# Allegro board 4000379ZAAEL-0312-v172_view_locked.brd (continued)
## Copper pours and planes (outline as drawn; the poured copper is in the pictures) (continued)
GND on TOP (solid shape): 66.62,92.71 65.82,92.71 65.82,94.84 66.62,94.84
GND on TOP (solid shape): 128.87,73.77 102.29,73.77 102.29,74.57 128.87,74.57
GND on TOP (solid shape): 66.62,82.91 70.15,82.91 70.15,82.11 65.82,82.11 65.82,86.42 66.62,86.42
GND on TOP (solid shape): 69.42,31.85 68.62,31.85 68.62,41 36.17,41 36.17,41.8 69.42,41.8
GND on TOP (solid shape): 69.42,21.1 50.29,21.1 50.29,21.9 68.62,21.9 68.62,29.74 69.42,29.74
GND on TOP (solid shape): 80.2,105.31 66.62,105.31 66.62,103.01 65.82,103.01 65.82,106.11 80.2,106.11
GND on TOP (solid shape): 89.62,96.38 88.82,96.38 88.82,105.31 82.61,105.31 82.61,106.11 89.62,106.11
GND on TOP (solid shape): 89.62,82.11 72.29,82.11 72.29,82.91 88.82,82.91 88.82,94.24 89.62,94.24
GND on TOP (solid shape): 94.87,74.57 100.15,74.57 100.15,73.77 94.07,73.77 94.07,99.32 94.87,99.32
GND on TOP (solid shape): 113.35,105.27 94.87,105.27 94.87,101.37 94.07,101.37 94.07,106.07 113.35,106.07
GND on TOP (solid shape): 137.07,101.39 136.27,101.39 136.27,105.27 117.79,105.27 117.79,106.07 137.07,106.07
GND on TOP (solid shape): 137.07,73.77 130.91,73.77 130.91,74.57 136.27,74.57 136.27,99.25 137.07,99.25
GND on TOP (solid shape): 24.64,72.64 24.89,72.39 25.91,72.39 26.29,72.01 26.29,65.79 22.86,65.79 22.86,73.91 24.64,73.91
GND on TOP (solid shape): 31.37,77.34 31.37,74.8 30.99,74.42 27.69,74.42 27.43,74.68 27.43,77.6 27.69,77.85 30.86,77.85
GND on TOP (solid shape): 32.77,70.36 32.77,67.18 30.99,67.18 30.23,67.94 30.23,70.1 30.61,70.48 30.61,70.99 32.13,70.99
GND on TOP (solid shape): 34.05,41 15.12,41 15.12,21.9 48.15,21.9 48.15,21.1 14.32,21.1 14.32,41.8 34.05,41.8
GND on TOP (solid shape): 41.72,78.17 41.72,76.14 41.4,75.82 40.01,75.82 39.69,76.14 39.69,77.72 39.75,77.79 40.07,77.79 40.13,77.85 40.13,78.61 41.27,78.61
GND on TOP (solid shape): 136.08,67.88 136.08,67.56 136.14,67.5 136.91,67.5 136.91,66.48 136.33,65.91 134.43,65.91 134.11,66.23 134.11,67.63 134.43,67.94 136.02,67.94
GND on TOP (solid shape): 61.09,74.93 61.09,72.77 60.9,72.58 59.69,72.58 59.56,72.71 59.56,73.6 59.63,73.66 59.82,73.66 60.13,73.98 60.13,74.93 60.26,75.06 60.96,75.06
GND on TOP (solid shape): 72.26,75.37 72.26,72.96 72.07,72.77 70.87,72.77 70.74,72.9 70.74,73.79 70.8,73.85 70.99,73.85 71.31,74.17 71.31,75.31 71.44,75.44 72.2,75.44
GND on BOTTOM (solid shape): 107.44,105.27 103.72,105.27 103.72,106.07 107.44,106.07
GND on BOTTOM (solid shape): 109.54,73.77 102.24,73.77 102.24,74.57 109.54,74.57
GND on BOTTOM (solid shape): 116.87,73.77 112.33,73.77 112.33,74.57 116.87,74.57
GND on BOTTOM (solid shape): 122.28,105.27 118.75,105.27 118.75,106.07 122.28,106.07
GND on BOTTOM (solid shape): 123.84,73.77 120.08,73.77 120.08,74.57 123.84,74.57
GND on BOTTOM (solid shape): 128.85,73.77 126.3,73.77 126.3,74.57 128.85,74.57
GND on BOTTOM (solid shape): 137.07,95.49 136.27,95.49 136.27,99.25 137.07,99.25
GND on BOTTOM (solid shape): 137.07,91.59 136.27,91.59 136.27,94.33 137.07,94.33
GND on BOTTOM (solid shape): 25.42,19.56 63,19.56 63,18.76 24.62,18.76 24.62,35.39 25.42,35.39
GND on BOTTOM (solid shape): 69.42,18.76 65.14,18.76 65.14,19.56 68.62,19.56 68.62,29.72 69.42,29.72
GND on BOTTOM (solid shape): 94.87,74.57 100.12,74.57 100.12,73.77 94.07,73.77 94.07,98.93 94.87,98.93
GND on BOTTOM (solid shape): 95.03,105.27 94.87,105.27 94.87,101.39 94.07,101.39 94.07,106.07 95.03,106.07
GND on BOTTOM (solid shape): 137.07,101.33 136.27,101.33 136.27,105.27 132.34,105.27 132.34,106.07 137.07,106.07
GND on BOTTOM (solid shape): 137.07,73.77 130.99,73.77 130.99,74.57 136.27,74.57 136.27,90.27 137.07,90.27
GND on BOTTOM (solid shape): 69.42,31.88 68.62,31.88 68.62,42.19 25.42,42.19 25.42,37.53 24.62,37.53 24.62,42.99 69.42,42.99
GND on BOTTOM: 39.88,169.62 55.37,169.62 55.37,150.37 59.88,145.86 62.87,145.86 62.87,143.26 64.14,141.99 64.14,122.43 65.53,121.03 145.92,121.03 146.18,121.28 146.18,138.05 135.25,148.97 135.25,167.74 133.74,169.26 145.14,162.48 149.62,150 149.62,20 143.87,6.13 130,0.38 20,0.38 6.13,6.13 0.38,20 0.38,150 5.56,163.28 18.35,169.55 18.35,156.46 19.37,155.45 25.97,155.45 25.97,154.11 27.24,152.84 30.42,152.84 31.05,152.21 32.83,152.21 32.83,152.02 32.32,151.51 32.32,149.48 33.21,148.59 37.66,148.59 38.54,149.48 38.54,151.38 37.97,151.96 37.21,151.96 36.96,152.21 36.96,153.23 38.48,153.23 39.88,154.62 ; 12 cut-outs
GND on L2: 149.62,20 143.87,6.13 130,0.38 20,0.38 6.13,6.13 0.38,20 0.38,150 5.56,163.28 18.35,169.55 18.35,156.46 19.37,155.45 25.97,155.45 25.97,154.11 27.24,152.84 30.42,152.84 31.05,152.21 32.83,152.21 32.83,152.02 32.32,151.51 32.32,149.48 33.21,148.59 37.66,148.59 38.54,149.48 38.54,151.38 37.97,151.96 37.21,151.96 36.96,152.21 36.96,153.23 38.48,153.23 39.88,154.62 39.88,169.62 55.37,169.62 55.37,150.37 59.88,145.86 62.87,145.86 62.87,143.26 64.14,141.99 64.14,122.43 65.53,121.03 145.92,121.03 146.18,121.28 146.18,138.05 135.25,148.97 135.25,167.74 133.74,169.26 145.14,162.48 149.62,150 ; 1 cut-out
GND on L3: 39.88,169.62 55.37,169.62 55.37,150.37 59.88,145.86 62.87,145.86 62.87,143.26 64.14,141.99 64.14,122.43 65.53,121.03 145.92,121.03 146.18,121.28 146.18,138.05 135.25,148.97 135.25,167.74 133.74,169.26 145.14,162.48 149.62,150 149.62,20 143.87,6.13 130,0.38 20,0.38 6.13,6.13 0.38,20 0.38,150 5.56,163.28 18.35,169.55 18.35,156.46 19.37,155.45 25.97,155.45 25.97,154.11 27.24,152.84 30.42,152.84 31.05,152.21 32.83,152.21 32.83,152.02 32.32,151.51 32.32,149.48 33.21,148.59 37.66,148.59 38.54,149.48 38.54,151.38 37.97,151.96 37.21,151.96 36.96,152.21 36.96,153.23 38.48,153.23 39.88,154.62 ; 2 cut-outs
PGND on TOP (solid shape): 10.54,105.54 8.51,105.54 8.51,109.6 10.54,109.6
PGND on TOP (solid shape): 14.48,105.41 12.57,105.41 12.57,109.66 14.48,109.66
PGND on TOP (solid shape): 19.05,136.27 19.05,127.38 18.29,126.62 12.95,126.62 12.45,127.13 12.45,136.72 12.76,137.03 18.29,137.03
PGND on TOP (solid shape): 49.21,98.68 49.21,91.06 48.96,90.81 40.64,90.81 40.13,91.31 40.13,98.81 40.58,99.25 48.64,99.25
PGND on TOP: 50.61,147.38 44.32,147.38 42.04,145.1 32.58,145.1 31.5,144.02 31.5,140.08 29.59,138.18 8.13,138.18 6.22,136.27 6.22,115.32 8.26,113.28 8.26,108.84 5.97,106.55 5.97,92.96 8.13,90.81 55.75,90.81 57.91,92.96 57.91,126.87 59.31,128.27 59.31,138.68 ; 2 cut-outs
PGND on BOTTOM, L3: 51.44,147.38 44.32,147.38 42.04,145.1 32.58,145.1 31.5,144.02 31.5,140.08 29.59,138.18 8.13,138.18 6.22,136.27 6.22,115.32 8.26,113.28 8.26,108.84 5.97,106.55 5.97,92.96 8.13,90.81 55.75,90.81 57.91,92.96 57.91,126.87 58.99,127.95 58.99,139.83
PGND on L2: 50.61,147.38 44.32,147.38 42.04,145.1 32.58,145.1 31.5,144.02 31.5,140.08 29.59,138.18 8.13,138.18 6.22,136.27 6.22,115.32 8.26,113.28 8.26,108.84 5.97,106.55 5.97,92.96 8.13,90.81 55.75,90.81 57.91,92.96 57.91,126.87 59.31,128.27 59.31,138.68
SVDD0_TRX on BOTTOM (solid shape): 78.18,92.35 78.18,91.01 78.05,90.89 77.37,90.89 77.24,91.01 77.24,91.56 77.15,91.65 75.41,91.65 75.29,91.53 75.29,90.71 75.18,90.61 74.32,90.61 74.24,90.68 74.24,92.36 74.28,92.39 78.14,92.39
VCC_0V6_DDR on TOP (solid shape): 129.92,24.84 129.92,23.44 129.95,23.44 130.45,22.94 130.45,21.67 128.12,21.67 127.48,22.3 127.48,24.61 127.81,24.94 129.82,24.94
VCC_0V6_DDR on BOTTOM (solid shape): 125.6,33.99 125.6,25.68 126.34,24.94 128.85,24.94 129.11,24.69 129.11,22.43 128.75,22.07 126.21,22.07 125.6,21.46 125.6,18.48 125.33,18.21 122.22,18.21 121.91,18.52 121.91,18.9 122.22,19.21 123.53,19.21 123.85,19.53 123.85,26.4 122.05,26.4 122.05,32.12 121.73,32.44 117.05,32.44 116.73,32.76 116.73,34.07 117.05,34.39 125.2,34.39
VCC_0V9_PRX321 on TOP (solid shape): 128.1,58.15 128.09,58.14 125.82,58.14 124.65,59.31 124.65,61.59 125.46,62.41 128.1,62.41
VCC_0V9_PRX321 on BOTTOM: 101.47,57.98 101.47,54.15 102.16,53.47 102.16,52.45 101.73,52.02 101.73,50.9 103.86,48.77 105.36,48.77 105.46,48.87 105.46,49.23 105.18,49.5 105.18,52.3 104.39,53.09 103.58,53.09 102.55,54.11 102.55,55.69 102.74,55.88 103.19,55.88 103.25,55.94 103.25,57.47 103.95,58.17 109.92,58.17 111.38,59.63 126.3,59.63 126.5,59.82 126.5,60.9 126.13,61.26 111.11,61.26 109.54,59.69 103.19,59.69
VCC_0V9_PRX321_XFI on BOTTOM (solid shape): 103.31,55.56 103.31,54.36 103.57,54.1 103.57,53.85 103.36,53.63 103.21,53.63 102.74,54.1 102.74,55.63 103.25,55.63
VCC_1V0_8261BE on TOP (solid shape): 69.34,89.41 69.34,87.44 68.96,87.06 65.41,87.06 64.64,86.3 64.64,83.82 64.45,83.63 62.74,83.63 62.55,83.82 62.55,88.07 64.2,89.73 69.02,89.73
VCC_1V0_8261BE on TOP (solid shape): 76.19,91.15 76.19,90.88 76.07,90.76 75.79,90.76 75.67,90.63 75.67,86.82 75.56,86.72 74.35,86.72 74.27,86.8 74.27,88.18 75.03,88.94 75.03,90.91 75.43,91.31 76.03,91.31
VCC_1V0_8261BE on BOTTOM (solid shape): 75.67,89.95 75.67,87.16 75.56,87.06 74.42,87.06 74.27,87.21 74.27,90.1 75.51,90.1
VCC_1V0_8261BE on BOTTOM (solid shape): 70.1,91.44 70.1,87.25 69.91,87.06 68.33,87.06 68.07,87.31 68.07,91.38 68.45,91.76 69.79,91.76
VCC_1V0_8261BE on BOTTOM (solid shape): 84.14,89.1 84.14,88.26 84.02,88.14 81.2,88.14 81.08,88.27 81.08,89.18 81.15,89.26 83.97,89.26
VCC_1V0_8261BE on BOTTOM (solid shape): 85.7,95.92 85.7,93.81 85.6,93.71 84.23,93.71 84.23,94.75 83.9,95.08 83.9,95.92 83.97,95.99 85.62,95.99
VCC_1V0_8261BE on BOTTOM (solid shape): 72.14,102.55 72.14,101.41 72.32,101.22 72.92,101.22 73.03,101.12 73.03,100.34 73,100.31 70.28,100.31 70.23,100.36 70.23,102.49 70.48,102.74 71.95,102.74
VCC_1V0_8261BE on L3: 68.71,102.74 71.95,102.74 72.14,102.55 72.14,100.39 71.02,99.28 71.02,90.35 72.36,89.01 73.41,89.01 74.75,90.35 79.67,90.35 80.19,90.87 80.19,94.9 84.2,94.9 84.2,88.33 83.61,87.74 76.91,87.74 76.23,87.05 68.33,87.05 68.07,87.31 68.07,102.11
VCC_1V9_8261BE on TOP (solid shape): 88.2,80.2 88.2,77.79 87.88,77.47 82.55,77.47 82.55,80.07 82.99,80.52 87.88,80.52
VCC_1V9_8261BE on BOTTOM (solid shape): 72.01,97.11 72.01,92.27 71.88,92.14 71.37,92.14 71.25,92.27 71.25,97.13 71.35,97.24 71.88,97.24
VCC_1V9_8261BE on BOTTOM (solid shape): 93.29,104.7 93.29,101.8 93.09,101.6 87.76,101.6 87.25,102.11 87.25,104.78 87.63,105.16 92.84,105.16
VCC_1V9_8261BE on BOTTOM (solid shape): 83.31,103.03 83.31,100.46 83.24,100.39 80.9,100.39 80.85,100.44 80.85,101.58 80.64,101.78 79.98,101.78 79.98,103.31 80.06,103.38 82.96,103.38
VCC_1V9_8261BE on L3: 74.68,90.58 79.47,90.58 80.01,91.12 80.01,95.03 83.82,95.03 83.82,100.84 84.07,101.1 87.69,101.1 88.33,100.46 88.33,83.19 85.47,80.33 85.47,77.98 85.98,77.47 87.88,77.47 91.69,81.28 91.69,99.69 93.29,101.3 93.29,103.36 93.07,103.59 81.86,103.59 81.23,102.95 81.23,96.65 78.38,96.65 78.38,92.56 72.9,92.56 72.67,92.79 72.67,97.21 71.35,97.21 71.2,97.06 71.2,90.56 72.49,89.26 73.36,89.26
VCC_1V35_DDR on TOP (solid shape): 135,30.61 135,28.51 134.68,28.19 131.04,28.19 130.09,29.15 130.09,30.87 134.73,30.87
VCC_1V35_DDR on BOTTOM (solid shape): 108.06,46.94 111.43,46.94 111.63,46.74 111.63,46.35 107.82,46.35 107.7,46.48 107.7,46.8 107.51,46.99 107.06,46.99 106.81,46.74 106.81,46.55 106.68,46.42 106.08,46.42 105.77,46.74 105.77,46.9 106.36,47.5 107.51,47.5
VCC_1V35_DDR on L3: 131.57,30.86 134.87,30.86 136.53,29.21 136.53,16.76 130.68,10.92 89.53,10.92 81.28,19.18 81.28,37.85 91.95,48.51 103.31,48.51 104.71,47.12 105.22,47.12 105.79,47.69 107.63,47.69 110.3,45.02 110.3,40.7 116.4,34.61 125.6,34.61 126.11,34.1 126.11,18.03 127.44,16.7 129.16,16.7 130.81,18.35 130.81,30.1
VCC_3V3_8261BE on BOTTOM (solid shape): 68.01,86.61 68.9,86.61 69.02,86.49 69.02,84.84 67.18,84.84 66.87,85.15 66.87,86.8 67.82,86.8
VCC_3V3_PON on TOP (solid shape): 54.8,83.5 54.8,64.96 51.63,64.96 51.63,83.38 52.01,83.76 54.55,83.76
VCC_3V3_PON on TOP (solid shape): 140.58,28.85 140.58,27.33 140.3,27.05 137.19,27.05 137.07,27.17 137.07,28.91 137.26,29.1 140.34,29.1
VCC_3V3_PON on TOP (solid shape): 65.79,32.19 66.8,32.19 66.93,32.07 66.93,29.46 66.87,29.4 64.6,29.4 64.53,29.47 64.53,31.97 64.87,32.32 65.66,32.32
VCC_3V3_PON on BOTTOM (solid shape): 126.01,77.14 126.01,72.06 125.5,71.55 124.43,71.55 124.03,71.96 124.03,77.29 125.86,77.29
VCC_3V3_PON on BOTTOM (solid shape): 66.9,31.32 66.9,30.43 66.7,30.23 65.68,30.23 65.51,30.4 65.51,31.19 65.81,31.5 66.73,31.5
VCC_3V3_PON on BOTTOM (solid shape): 47.69,34.73 47.69,31.62 48.07,31.24 48.9,31.24 49.15,30.99 49.15,29.91 48.96,29.72 46.42,29.72 46.23,29.91 46.23,34.73 46.42,34.92 47.5,34.92
VCC_3V3_PON on L3 (solid shape): 141.11,28.38 141.11,27.25 138.67,27.25 138.34,27.58 138.34,28.69 138.52,28.87 140.63,28.87
VCC_3V3_PON on L3 (solid shape): 66.9,31.32 66.9,30.45 65.96,29.51 65.2,29.51 64.99,29.72 64.99,30.67 65.82,31.5 66.73,31.5
VCC_3V3_PON on L3 (solid shape): 126.03,72.87 126.03,66.45 126.26,66.22 126.26,64.97 123.72,64.97 123.72,66.14 124.03,66.45 124.03,73.03 124.28,73.28 125.63,73.28
VCC_3V3_PON on L3: 52.83,67.37 52.83,49.78 43.69,40.64 43.69,20.07 44.13,19.62 65.72,19.62 66.48,20.38 66.48,22.67 65.02,22.67 65.02,22.16 63.94,21.08 47.56,21.08 46.86,21.78 46.86,28.89 47.69,29.72 47.69,33.91 47.43,34.16 46.48,34.16 46.04,34.61 46.04,39.62 54.8,48.39 54.8,67.37
VCC_20V0_SYS on TOP (solid shape): 19.62,147.7 19.62,141.73 19.24,141.35 14.92,141.35 14.67,141.6 14.67,147.38 15.18,147.89 19.43,147.89
VCC_20V0_SYS on TOP (solid shape): 70.87,63.56 70.87,61.85 70.61,61.59 68.52,61.59 68.14,61.98 68.14,63.63 68.45,63.94 70.48,63.94
VCC_20V0_SYS on TOP (solid shape): 93.66,75.82 93.66,75.5 79.76,61.59 79.44,61.59 78.93,62.1 78.93,62.55 92.77,76.39 93.09,76.39
VCC_20V0_SYS on TOP (solid shape): 131.64,45.91 131.64,43.43 131.38,43.18 129.92,43.18 129.54,43.56 129.54,45.91 129.79,46.16 131.38,46.16
VCC_20V0_SYS on TOP (solid shape): 100.71,83.25 100.71,82.19 100.5,81.98 98.03,81.98 97.28,81.23 97.28,78.93 97.09,78.74 96.27,78.74 96.01,78.99 96.01,81.84 97.61,83.44 100.52,83.44
VCC_20V0_SYS on TOP (solid shape): 123.63,66.87 123.63,59.37 125.54,57.47 128.52,57.47 128.71,57.28 128.71,56.13 128.46,55.88 124.78,55.88 121.86,58.8 121.86,66.93 122.05,67.12 123.38,67.12
VCC_20V0_SYS on TOP (solid shape): 22.08,77.2 22.08,63.71 23.69,62.1 31.88,62.1 33.72,63.94 58.99,63.94 59.37,63.56 59.37,61.85 59.12,61.59 42.16,61.59 41.02,60.45 41.02,56.13 39.88,54.99 17.8,54.99 16.31,56.48 16.31,77.52 16.52,77.72 21.56,77.72
VCC_20V0_SYS on L3 (solid shape): 123.63,63.06 123.32,62.74 121.28,62.74 121.28,64.01 123.63,64.01
VCC_20V0_SYS on L3 (solid shape): 82.36,62.74 80.9,62.74 79.76,61.59 57.02,61.59 56.64,61.98 56.64,63.63 57.02,64.01 82.36,64.01
VCC_20V0_SYS on L3 (solid shape): 97.28,81.34 97.28,79.12 91.88,73.72 91.5,73.72 90.93,74.3 90.93,74.55 96.01,79.63 96.01,81.34 96.2,81.53 97.09,81.53
VCC_20V0_SYS on L3 (solid shape): 131.64,56.07 131.64,45.02 131.38,44.77 129.73,44.77 129.54,44.96 129.54,55.63 129.29,55.88 127.44,55.88 127.19,56.13 127.19,57.21 127.44,57.47 130.24,57.47
VCC_20V0_SYS on L3: 19.37,144.4 19.62,144.15 19.62,141.73 19.24,141.35 5.84,141.35 3.81,139.32 3.81,75.31 5.46,73.66 19.81,73.66 20.19,73.28 20.19,70.36 19.81,69.98 3.81,69.98 1.02,72.77 1.02,140.59 4.83,144.4
VCC_20V0_USB_PD on TOP (solid shape): 26.23,160.4 26.23,157.16 25.78,156.72 19.11,156.72 19.11,160.34 20.19,161.42 25.21,161.42
VCC_20V0_USB_PD on L3: 34.95,161.8 34.95,166.04 34.24,166.75 31.04,166.75 29.95,165.66 29.95,162.51 29.54,162.1 26.24,162.1 25.55,161.42 21.78,161.42 21.4,161.04 21.4,159.13 21.7,158.83 25.98,158.83 27.5,160.34 30.73,160.34 31.11,160.72 31.11,165.1 31.88,165.86 33.07,165.86 33.73,165.2 33.73,161.7 33.86,161.57 34.72,161.57
VDD_RX on BOTTOM (solid shape): 50.46,30.91 50.46,30.05 50.93,29.59 51.88,29.59 52.07,29.4 52.07,28.83 51.75,28.51 49.72,28.51 49.53,28.7 49.53,30.85 49.66,30.99 50.39,30.99
VDD_RX2 on TOP (solid shape): 67.06,28.57 67.06,23.51 66.92,23.36 65.89,23.36 65.82,23.44 65.82,26.62 65.74,26.7 64.73,26.7 64.62,26.81 64.62,27.65 64.52,27.75 64.52,28.51 64.96,28.96 66.67,28.96
VDD_TX on BOTTOM (solid shape): 50.29,37.18 50.29,35.88 49.78,35.37 46.55,35.37 46.42,35.5 46.42,37.53 46.55,37.66 49.82,37.66
VDD_TX on L3: 59.03,37.54 59.03,34.59 56.38,31.94 54.55,31.94 53.02,33.46 49.85,33.46 47.75,35.56 47.75,37.59 49.02,38.86 57.71,38.86
(no net) on TOP: 39.88,169.62 55.37,169.62 55.37,150.37 59.88,145.86 62.87,145.86 62.87,143.26 64.14,141.99 64.14,122.43 65.53,121.03 145.92,121.03 146.18,121.28 146.18,138.05 135.25,148.97 135.25,167.74 133.74,169.26 145.14,162.48 149.62,150 149.62,20 143.87,6.13 130,0.38 20,0.38 6.13,6.13 0.38,20 0.38,150 5.56,163.28 18.35,169.55 18.35,156.46 19.37,155.45 25.97,155.45 25.97,154.11 27.24,152.84 30.42,152.84 31.05,152.21 32.83,152.21 32.83,152.02 32.32,151.51 32.32,149.48 33.21,148.59 37.66,148.59 38.54,149.48 38.54,151.38 37.97,151.96 37.21,151.96 36.96,152.21 36.96,153.23 38.48,153.23 39.88,154.62 ; 17 cut-outs
DUT_AVDDHC_3V3 on TOP (solid shape): 122.3,100 122.3,95.71 121.03,94.43 121.03,93.34 120.61,92.92 117.54,92.92 117.1,93.37 116.29,93.37 115.97,93.05 114.51,93.05 114.45,93.11 114.45,94.38 114.77,94.7 116.9,94.7 117.32,94.28 117.32,93.88 117.63,93.57 118.85,93.57 119.21,93.94 119.21,95.65 120.73,97.17 120.73,99.59 120.37,99.95 120.27,99.95 120.27,100.46 121.84,100.46
DUT_AVDDHC_3V3 on TOP (solid shape): 121.75,89.7 121.75,89.06 121.23,88.54 120.35,88.54 118.58,86.76 116.42,86.76 116.29,86.89 115.4,86.89 115.02,86.51 114.83,86.51 114.09,87.24 112.33,87.24 110.07,84.98 108.1,84.98 107.7,84.58 107.7,83.44 107.31,83.06 105.66,83.06 105.47,83.25 105.47,85.47 106.02,86.02 109.39,86.02 111.27,87.9 111.27,88.67 111.08,88.86 111.08,89.11 111.21,89.24 114.96,89.24 116.73,87.46 117.88,87.46 120.35,89.94 121.51,89.94
DUT_AVDDHC_3V3 on BOTTOM (solid shape): 99.34,84.07 99.52,83.9 106.79,83.9 107.11,83.58 107.11,83.34 106.83,83.06 101.73,83.06 101.27,82.6 101.27,79.91 100.81,79.91 98.68,82.04 98.68,84.76 99.34,84.76
DUT_AVDDLC_0V95 on TOP (solid shape): 122.64,91.14 122.64,90.64 122.35,90.34 121.51,90.34 121.31,90.55 121.31,91.16 121.48,91.33 122.45,91.33
DUT_AVDDLC_0V95 on TOP (solid shape): 114.19,86.57 114.19,85.11 114.13,85.05 112.73,85.05 112.54,84.86 112.54,82.19 112.29,81.94 109.94,81.94 109.62,82.25 109.62,83.78 109.94,84.09 110.7,84.09 110.83,84.22 110.83,85.12 112.47,86.76 114,86.76
DUT_AVDDLC_0V95 on TOP (solid shape): 127.71,93.57 134.52,93.57 134.8,93.29 134.8,92.58 134.52,92.3 126.72,92.3 126.58,92.16 124.99,92.16 124.23,92.92 123.66,92.92 123.47,92.73 123.47,92.55 121.64,92.55 121.43,92.76 121.43,94.06 121.56,94.19 121.81,94.19 122.13,93.87 123.4,93.87 124.1,94.57 126.71,94.57
DUT_AVDDLC_0V95 on TOP (solid shape): 123.98,88.47 123.98,88.06 123.63,87.71 123.39,87.71 123.19,87.51 123.19,86.21 123.8,85.6 124.26,85.6 125.3,84.56 132.33,84.56 132.33,83.14 121.24,83.14 120.95,83.43 120.95,84.03 123.17,84.03 123.6,84.45 123.6,84.84 122.89,85.55 121.79,85.55 121.36,85.98 121.36,86.33 121.64,86.61 121.64,87.63 121.33,87.94 121.33,88.08 121.48,88.24 121.64,88.24 122.07,88.67 123.78,88.67
DUT_AVDDLC_0V95 on TOP (solid shape): 106.07,100.56 106.07,98.88 106.76,98.2 115.92,98.2 116.13,97.99 116.13,96.08 116.02,95.98 115.54,95.98 115.43,96.1 115.43,96.51 115.19,96.75 109.17,96.75 108.74,96.32 108.74,95.25 109.37,94.61 113.48,94.61 114.04,94.05 114.04,91.32 114.3,91.06 114.3,89.96 114.12,89.78 113.74,89.78 113.64,89.89 113.64,90.22 113.46,90.39 113.05,90.39 112.95,90.49 112.95,91.19 113.26,91.49 113.26,92.27 113.08,92.45 109.86,92.45 108.92,93.4 108.15,93.4 106.81,94.74 104.06,94.74 103.45,95.35 103.45,98.96 103.2,99.21 102.23,99.21 101.92,99.53 101.92,101.22 102.11,101.41 105.22,101.41
EAR_GND on TOP, L2: 57.48,169.62 130,169.62 130.51,169.61 131.02,169.59 133.48,167.13 133.48,148.21 144.27,137.41 144.27,123 144.02,122.75 141.86,122.75 141.48,123.13 141.48,134.62 130.43,145.67 130.43,157.48 125.35,162.56 125.35,165.48 123.95,166.88 113.03,166.88 111.89,165.74 111.89,162.69 111.12,161.93 109.47,161.93 108.58,162.81 108.58,166.12 107.82,166.88 95.89,166.88 95.25,166.24 95.25,162.69 94.49,161.93 92.84,161.93 91.95,162.81 91.95,165.61 90.68,166.88 79.25,166.88 78.61,166.24 78.61,162.69 77.85,161.93 76.07,161.93 75.31,162.69 75.31,165.99 74.42,166.88 63.25,166.88 61.59,165.23 61.59,162.43 60.45,161.29 60.45,151.26 62.87,148.84 62.87,147.51 60.77,147.51 57.15,151.13 57.15,169.29
EAR_GND on BOTTOM: 57.48,169.62 130,169.62 130.51,169.61 131.02,169.59 133.48,167.13 133.48,148.21 135.38,146.3 135.38,144.4 134.75,143.76 132.33,143.76 130.43,145.67 130.43,157.48 125.35,162.56 125.35,165.48 123.95,166.88 113.03,166.88 111.89,165.74 111.89,162.69 111.12,161.93 109.47,161.93 108.58,162.81 108.58,166.12 107.82,166.88 95.89,166.88 95.25,166.24 95.25,162.69 94.49,161.93 92.84,161.93 91.95,162.81 91.95,165.61 90.68,166.88 79.25,166.88 78.61,166.24 78.61,162.69 77.85,161.93 76.07,161.93 75.31,162.69 75.31,165.99 74.42,166.88 63.25,166.88 61.59,165.23 61.59,162.43 60.45,161.29 60.45,151.26 62.87,148.84 62.87,147.51 60.77,147.51 57.15,151.13 57.15,169.29
EAR_GND on BOTTOM, L3: 135.25,146.43 65.28,146.43 61.59,150.11 59.88,148.4 64.77,143.51 132.59,143.51 141.48,134.62 141.48,126.36 141.1,125.98 64.9,125.98 64.64,125.73 64.64,122.94 64.77,122.81 143.89,122.81 144.4,123.32 144.4,137.29
EAR_GND on L3: 57.48,169.62 130,169.62 130.51,169.61 131.02,169.59 133.48,167.13 133.48,148.21 135.38,146.3 135.38,144.4 134.75,143.76 132.33,143.76 130.43,145.67 130.43,157.48 125.35,162.56 125.35,165.48 123.95,166.88 113.03,166.88 111.89,165.74 111.89,162.69 111.12,161.93 109.47,161.93 108.58,162.81 108.58,166.12 107.82,166.88 95.89,166.88 95.25,166.24 95.25,162.69 94.49,161.93 92.84,161.93 91.95,162.81 91.95,165.61 90.68,166.88 79.25,166.88 78.61,166.24 78.61,162.69 77.85,161.93 76.07,161.93 75.31,162.69 75.31,165.99 74.42,166.88 63.25,166.88 61.59,165.23 61.59,162.43 60.45,161.29 60.45,151.26 62.93,148.78 62.93,147.57 62.8,147.45 60.83,147.45 57.15,151.13 57.15,169.29
PSE_54V0_P2- on TOP (solid shape): 52.32,143.38 52.32,140.72 52.01,140.4 42.86,140.4 41.91,141.35 41.91,143.45 42.04,143.57 52.13,143.57
PSE_54V0_P3- on TOP (solid shape): 57.15,129.92 57.15,128.84 56.83,128.52 49.53,128.52 48.83,129.22 46.61,129.22 46.61,130.68 47.24,131.32 55.75,131.32
UPGND on TOP, BOTTOM, L2, L3: 19.49,169.67 38.67,169.67 39.12,169.23 39.12,154.94 38.16,153.99 36.32,153.99 36.2,153.86 36.2,151.83 36.58,151.45 37.4,151.45 37.78,151.07 37.78,149.8 37.34,149.35 33.53,149.35 33.08,149.8 33.08,151.19 33.59,151.7 33.59,152.72 33.34,152.97 31.37,152.97 30.73,153.61 27.56,153.61 26.73,154.43 26.73,155.83 26.35,156.21 19.68,156.21 19.11,156.78 19.11,169.29
VOUT on TOP (solid shape): 24.96,153.48 24.96,151.64 25.27,151.32 27.43,151.32 27.43,149.35 27.05,148.97 15.49,148.97 15.37,149.1 15.37,153.16 15.88,153.67 24.77,153.67
VREFCA on TOP (solid shape): 136.35,20.75 136.35,19.61 136.12,19.38 131.65,19.38 130.58,18.31 130.58,17.37 130.33,17.12 128.75,17.12 128.47,17.4 128.47,20.37 128.6,20.5 130.23,20.5 130.73,21.01 136.09,21.01
VREFCA on BOTTOM (solid shape): 130.61,18.67 130.61,17.12 127.58,17.12 127.43,17.28 127.43,18.54 128.22,19.33 129.95,19.33
N18711395 on TOP (solid shape): 62.97,26.44 62.97,25.5 62.84,25.38 62.04,25.38 60.22,23.56 56.71,23.56 56.64,23.62 56.64,25.27 57.59,26.23 60.83,26.23 61.09,26.48 62.93,26.48
N18711397 on TOP (solid shape): 64.32,26.6 64.32,23.45 64.23,23.37 61.92,23.37 61.66,23.63 61.66,24.78 62.06,25.18 62.91,25.18 63.12,25.38 63.12,26.58 63.21,26.67 64.24,26.67
N18712445 on BOTTOM (solid shape): 54.17,31.37 54.17,30.9 53.43,30.16 52.26,30.16 52.07,29.97 51.05,29.97 50.86,30.16 50.86,30.86 50.99,30.99 53.02,30.99 53.59,31.56 53.98,31.56
N19149157 on TOP (solid shape): 133.32,24.79 133.32,23.55 133.17,23.39 130.45,23.39 130.4,23.44 130.4,25.02 130.48,25.1 133.02,25.1
N19149173 on TOP (solid shape): 136.21,23.3 136.21,21.4 136.08,21.27 135.51,21.27 135.38,21.4 135.38,23.24 135.57,23.43 136.08,23.43
N19149206 on TOP (solid shape): 136.59,24.38 135.57,24.38 135.45,24.51 135.45,28.64 136.59,28.64
N19149219 on TOP (solid shape): 133.73,27.75 133.73,25.97 134.18,25.53 134.18,24.38 133.54,24.38 133.48,24.45 133.48,24.96 132.78,25.65 132.78,27.56 133.03,27.81 133.67,27.81
N19149964 on TOP (solid shape): 9.63,60.02 9.63,56.39 9.23,55.99 6.08,55.99 5.7,56.37 5.7,60.18 6.1,60.58 9.07,60.58
N19149982 on TOP (solid shape): 12.58,60.35 12.58,57.99 11.78,57.2 11.78,51.76 11.48,51.45 10.27,51.45 9.95,51.77 9.95,60.08 10.46,60.59 12.33,60.59
N19164772 on BOTTOM (solid shape): 46.8,130.24 46.8,127.95 46.67,127.83 41.27,127.83 41.02,128.08 41.02,130.43 41.15,130.56 46.48,130.56
N19164775 on TOP (solid shape): 43.05,128.4 48.32,128.4 48.64,128.08 48.64,126.11 48.32,125.79 41.97,125.79 40.83,126.94 40.83,129.22 40.89,129.29 42.16,129.29
N19165359 on BOTTOM (solid shape): 43.94,134.94 43.94,130.94 43.75,130.75 41.08,130.75 40.96,130.87 40.96,134.87 41.21,135.13 43.75,135.13
N19165523 on TOP (solid shape): 48.7,134.87 48.7,132.02 48.39,131.7 46.99,131.7 45.53,130.24 43.56,130.24 43.37,130.43 43.37,134.68 43.69,135 48.58,135
N19165523 on BOTTOM (solid shape): 48.7,134.87 48.7,133.1 48.58,132.97 46.61,132.97 46.42,133.16 46.42,134.87 46.55,135 48.58,135
N19177080 on BOTTOM (solid shape): 43.88,139.51 43.88,135.38 43.75,135.25 41.21,135.25 40.96,135.51 40.96,139.51 41.21,139.76 43.62,139.76
N19177140 on TOP (solid shape): 48.77,139.7 48.77,135.64 48.45,135.32 43.43,135.32 43.37,135.38 43.37,139.95 43.56,140.14 48.32,140.14
N19177140 on BOTTOM (solid shape): 48.77,138.49 48.77,136.59 48.7,136.53 46.67,136.53 46.42,136.78 46.42,138.49 46.67,138.75 48.51,138.75
N19177597 on BOTTOM (solid shape): 38.93,142.37 38.93,141.6 38.61,141.29 37.59,141.29 37.15,140.84 37.15,140.08 36.89,139.83 33.91,139.83 33.08,140.65 33.08,142.05 33.66,142.62 38.67,142.62
N19177618 on TOP (solid shape): 39.43,143.51 40.2,143.51 40.39,143.32 40.39,141.48 40.32,141.41 34.1,141.41 33.66,141.86 33.66,144.15 33.85,144.34 38.61,144.34
N19198143 on TOP (solid shape): 29.02,131.64 29.02,125.41 29.21,125.22 30.86,125.22 31.11,124.97 31.11,122.75 30.86,122.49 26.48,122.49 26.29,122.68 26.29,131.25 26.73,131.7 28.96,131.7
N19198187 on TOP (solid shape): 35.31,121.41 35.31,117.28 34.29,116.27 26.86,116.27 26.04,117.09 26.04,119 32.19,119 33.02,118.17 34.23,118.17 34.35,118.3 34.35,121.35 34.54,121.54 35.18,121.54
N19198218 on TOP (solid shape): 38.04,121.22 39.05,121.22 39.88,120.4 49.78,120.4 50.16,120.02 50.16,117.41 49.66,116.9 37.4,116.9 36.83,117.47 36.83,121.41 37.85,121.41
N19198237 on TOP (solid shape): 41.72,125.54 42.67,125.54 42.99,125.22 42.99,124.46 42.86,124.33 40.51,124.33 39.81,125.03 37.08,125.03 36.89,125.22 36.89,126.94 37.02,127.06 40.2,127.06
N19198365 on TOP (solid shape): 34.04,121.41 34.04,118.55 33.91,118.43 33.15,118.43 32.83,118.75 32.83,121.48 32.96,121.6 33.85,121.6
N19201777 on TOP (solid shape): 14.35,77.47 14.35,73.41 13.84,72.9 11.81,72.9 11.18,72.26 11.18,70.36 11.56,69.98 12.7,69.98 13.08,69.6 13.08,62.74 5.59,62.74 4.95,63.37 4.95,77.34 5.33,77.72 14.1,77.72
N19201879 on TOP (solid shape): 26.29,77.09 26.29,72.77 26.16,72.64 25.15,72.64 24.89,72.9 24.89,73.91 23.75,75.06 23.75,77.34 24.13,77.72 25.65,77.72
N19202018 on TOP (solid shape): 15.75,71.88 15.75,64.14 14.48,64.14 13.84,64.77 13.84,69.6 13.08,70.36 12.06,70.36 11.94,70.48 11.94,72.14 12.06,72.26 15.37,72.26
N19202225 on TOP (solid shape): 27.62,113.54 31.88,113.54 32,113.41 32,111.12 31.62,110.74 25.4,110.74 24.57,111.57 24.57,112.59 24.19,112.97 22.23,112.97 22.03,112.78 22.03,111.19 21.78,110.93 18.8,110.93 18.35,110.49 18.35,108.71 15.81,108.71 13.08,111.44 13.08,120.21 13.4,120.52 20.64,120.52
N19202261 on TOP (solid shape): 53.85,112.52 53.85,106.74 52.32,105.22 40.83,105.22 39.5,106.55 39.5,109.6 38.35,110.74 32.89,110.74 32.51,111.12 32.51,113.41 32.64,113.54 52.83,113.54
N19202468 on TOP (solid shape): 24.26,112.46 24.26,111.51 25.27,110.49 28.57,110.49 29.34,109.73 29.34,105.54 23.75,105.54 23.75,107.89 22.48,109.16 22.48,112.52 22.61,112.65 24.07,112.65
N19492059 on TOP (solid shape): 135.25,69.72 135.25,68.83 135.45,68.64 136.72,68.64 136.78,68.58 136.78,68.26 136.72,68.2 134.43,68.2 133.92,67.69 122.07,67.69 122.07,69.27 122.76,69.95 135.03,69.95
N19492096 on TOP (solid shape): 144.27,61.91 144.27,60.2 142.21,58.14 129.21,58.14 129.21,62.23 143.95,62.23
N19492579 on TOP (solid shape): 144.34,67.63 144.34,65.6 144.08,65.34 137.99,65.34 137.99,67.56 137.86,67.69 136.4,67.69 136.33,67.75 136.33,68.01 138.24,68.01 138.68,68.45 143.51,68.45
N19492605 on TOP (solid shape): 138.81,68.83 138.18,68.2 137.1,68.2 137.1,68.58 137.16,68.64 137.48,68.64 137.73,68.9 137.73,69.34 137.92,69.53 138.81,69.53
N19494174 on TOP (solid shape): 133.39,32.75 132.64,32 130.21,32 129.97,32.25 129.97,39.34 133.39,39.34
N19494229 on TOP (solid shape): 137.52,40.07 137.71,39.88 138.34,39.88 138.4,39.81 138.4,39.56 129.92,39.56 129.92,42.55 137.52,42.55
N19494302 on TOP (solid shape): 138.4,38.99 137.35,38.99 137.35,37.38 137.47,37.25 137.47,35.75 136.63,34.9 134.75,34.9 134.75,39.19 134.92,39.37 138.4,39.37
N19496414 on TOP (solid shape): 39.5,78.42 39.5,76.14 40.01,75.63 40.01,64.77 39.75,64.52 38.04,64.52 37.66,64.9 37.66,76.64 37.97,76.96 38.86,76.96 39.05,77.15 39.05,78.42 39.12,78.49 39.43,78.49
N19496646 on TOP (solid shape): 50.61,85.09 50.61,72.83 50.29,72.52 47.18,72.52 46.74,72.96 46.74,86.17 46.86,86.3 49.4,86.3
N19496749 on TOP (solid shape): 43.05,86.11 43.05,79.76 42.99,79.69 40.13,79.69 40.01,79.57 40.01,78.11 39.94,78.04 39.69,78.04 39.69,79.95 39.24,80.39 39.24,85.22 40.2,86.17 42.99,86.17
N19496764 on TOP (solid shape): 39.5,79.88 39.5,78.8 39.12,78.8 39.05,78.87 39.05,79.18 38.8,79.44 38.35,79.44 38.16,79.63 38.16,80.52 38.86,80.52
N19531807 on TOP (solid shape): 26.86,152.97 28.89,152.97 28.89,151.57 28.83,151.51 25.72,151.51 25.53,151.7 25.53,153.29 25.59,153.35 26.48,153.35
N19561994 on TOP (solid shape): 65.15,82.36 65.15,74.8 64.9,74.55 62.93,74.55 62.48,74.99 62.48,82.36 62.67,82.55 64.96,82.55
N19562054 on TOP (solid shape): 58.86,71.69 59.18,71.37 59.18,64.83 58.8,64.45 57.28,64.45 56.96,64.77 56.96,71.63 57.4,72.07 58.04,72.07 58.61,72.64 58.61,73.34 58.86,73.34
N19562127 on TOP (solid shape): 59.37,72.58 59.5,72.45 60.96,72.45 61.28,72.77 61.28,73.15 61.47,73.34 64.96,73.34 65.21,73.09 65.21,71.82 64.83,71.44 59.5,71.44 59.12,71.82 59.12,73.34 59.37,73.34
N19563922 on TOP (solid shape): 81.41,79.06 81.41,76.26 80.77,75.63 73.85,75.63 73.47,76.01 73.47,78.87 73.98,79.38 81.09,79.38
N19563982 on TOP (solid shape): 70.1,71.82 70.42,71.5 70.42,64.96 70.04,64.58 68.52,64.58 68.2,64.9 68.2,71.75 68.64,72.2 69.28,72.2 69.85,72.77 69.85,73.47 70.1,73.47
N19564055 on TOP (solid shape): 79.76,74.04 79.76,72.01 79.38,71.63 70.55,71.63 70.29,71.88 70.29,73.47 70.61,73.47 70.61,72.77 70.74,72.64 72.2,72.64 72.45,72.9 72.45,73.98 72.58,74.1 79.69,74.1
N19565593 on TOP (solid shape): 100.58,101.31 100.58,96.57 100.36,96.34 98.25,96.34 97.95,96.64 97.95,101.32 98.18,101.55 100.34,101.55
N19565653 on TOP (solid shape): 102.95,90.73 102.95,82.25 102.62,81.92 101.35,81.92 101.22,82.04 101.22,88.29 101.88,88.95 101.88,90.55 101.56,90.87 100.97,90.87 100.97,91.19 102.49,91.19
N19565726 on TOP (solid shape): 102.92,98.7 102.92,91.92 102.37,91.38 100.97,91.38 100.97,91.63 101.59,91.63 101.83,91.87 101.83,98.86 102.77,98.86
N20369270 on BOTTOM (solid shape): 90.17,111.51 90.17,106.99 89.86,106.68 87.63,106.68 87.47,106.84 87.47,111.98 87.54,112.05 89.62,112.05

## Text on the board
Ref Des/Silkscreen Bottom: A0AA
User.Comments: W3.3_S10.7_W3.3_G7 | W4.5_S6.5_W4.5_G7 | W4.2_S6.5_W4.2_G7 | Deliver data time: 2025/03/12 | MSTC confidential information and must be deleted in one-day after the review process is done. | The Layout and Gerber file released by Mitrastar to | RealTek | to any third party without Mitrastar's prior written approval. | whether direct or indirect, suffered by Mitrastar. | shall not use or modify such Layout and Gerber file for | is for the sole purpose of "internal technical review" and for | any other purpose except the above or disclose the  Layout and Gerber file | Should | violate or breach aforementioned rule, | GPT-5340K v1 | will be liable for any and all damages, | project only.
Ref Des/Silkscreen Top: A0 | 45-040-000379Z | AA
User.6: F
User.24: FIGURE | FINISHED_SIZE | 8.0 | 10.0 | 12.0 | 34.0 | 36.0 | 40.0 | 41.0 | 49.0 | 52.0 | 71.0 | 217.0 | 24.0 | 128.0 | 48.0x24.0 | 50.0x28.0 | 75.0x24.0 | 79.0x28.0 | 34.0x20.0 | ROTATION | - | 0.000 | 90.000 | DRILL CHART: TOP to BOTTOM | ALL UNITS ARE IN MILS | TOLERANCE_DRILL | +3.0/-3.0 | +2.0/-2.0 | TOLERANCE_TRAVEL | PLATED | NON-PLATED | QTY | 165 | 1458 | 1340 | 32 | 3 | 2 | 8 | 4 | 1 | 9 | 6 | 3056 | TOTAL HOLES:
